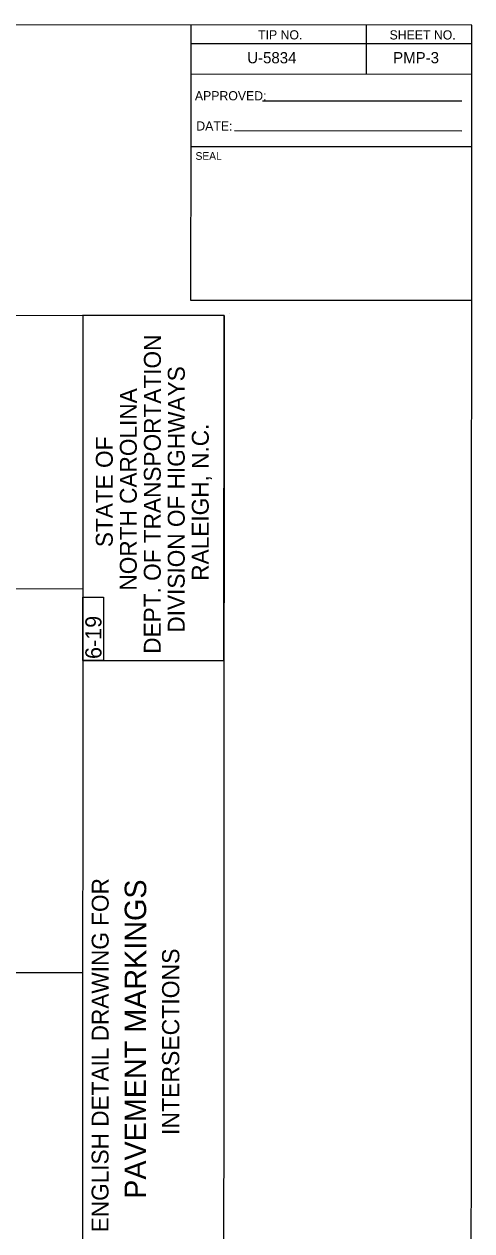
# Model space of a CAD drawing. Extents: x 50667 to 52386, y 46650 to 50479.
# Drawn here: x 52036 to 52336, y 47063 to 47871 of the extents above; entities that cross this region are included whole.
import ezdxf

# ---------------------------------------------------------------- set-up
doc = ezdxf.new("R2010")
doc.units = 0
for name, color, linetype in [('Default', 7, 'Continuous'), ('DEV TUBULAR MARKER SECTIONAL VIEW CELL', 7, 'Continuous'), ('Exist Right of Way Monument Text', 7, 'Continuous'), ('Exist Vertical Profile Ground Line', 7, 'Continuous'), ('Exist Vertical Profile Vertical Axis Label', 7, 'Continuous'), ('Old_Level_20', 7, 'Continuous'), ('Sheet Sticker Preliminary CELL', 7, 'Continuous'), ('Text', 7, 'Continuous'), ('TSCONFLICT', 7, 'Continuous')]:
    doc.layers.add(name, color=color, linetype=linetype)

msp = doc.modelspace()

# ---------------------------------------------------------------- linework, layer by layer
at = {"layer": 'Default'}
for p, q in [((52075.53, 47492.74), (50973.75, 47493.26)), ((52075.41, 47236.01), (50973.63, 47236.53))]:
    msp.add_line(p, q, dxfattribs=at)
at = {"layer": 'DEV TUBULAR MARKER SECTIONAL VIEW CELL'}
msp.add_lwpolyline([(50879.23, 46906.71), (50879.58, 47676.39), (52169.91, 47675.79), (52169.55, 46906.11)], close=True, dxfattribs=at)
at = {"layer": 'Exist Right of Way Monument Text'}
msp.add_lwpolyline([(52335.61, 47869.9), (50830.4, 47870.6), (50829.91, 46815.38), (52335.12, 46814.68)], close=True, dxfattribs=at)
at = {"layer": 'Exist Vertical Profile Ground Line'}
for p, q in [((52265.08, 47837.27), (52265.09, 47869.94)), ((52265.08, 47844.88), (52265.09, 47869.94)), ((52335.61, 47869.9), (52335.61, 47869.9)), ((52147.87, 47857.73), (52265.09, 47857.66)), ((52265.09, 47857.66), (52335.6, 47857.63)), ((52147.86, 47837.33), (52335.59, 47837.23)), ((52195.73, 47819.36), (52328.87, 47819.3)), ((52176.97, 47799.38), (52328.86, 47799.31))]:
    msp.add_line(p, q, dxfattribs=at)
at = {"layer": 'Old_Level_20'}
msp.add_line((52173.51, 47677.08), (52173.51, 47677.08), dxfattribs=at)
at = {"layer": 'Sheet Sticker Preliminary CELL'}
msp.add_lwpolyline([(52075.51, 47444.92), (52169.8, 47444.88), (52169.91, 47675.79), (52075.61, 47675.83), (52075.26, 46906.16), (52169.55, 46906.11), (52169.57, 46929.69), (52075.27, 46929.73), (52075.27, 46943.87), (52169.57, 46943.82)], dxfattribs=at)
at = {"layer": 'Text'}
msp.add_lwpolyline([(52089.26, 47444.92), (52075.51, 47444.92), (52075.53, 47487.28), (52089.28, 47487.28)], close=True, dxfattribs=at)
at = {"layer": 'TSCONFLICT'}
for p, q in [((52147.87, 47844.94), (52147.88, 47869.99)), ((52147.85, 47797.58), (52147.87, 47844.94)), ((52147.79, 47685.74), (52147.85, 47797.58)), ((52147.84, 47788.8), (52335.57, 47788.71)), ((52335.52, 47685.65), (52147.79, 47685.74))]:
    msp.add_line(p, q, dxfattribs=at)

# ---------------------------------------------------------------- texts
at = {"layer": 'Default'}
for s, height, p in [('PAVEMENT MARKINGS', 14.3748, (52117.79, 47084.82)), ('INTERSECTIONS', 11.4998, (52139.95, 47127.5))]:
    msp.add_text(s, height=height, rotation=89.97341, dxfattribs=at).set_placement(p)
at = {"layer": 'Exist Vertical Profile Ground Line'}
for s, height, p in [('TIP NO.', 6.134, (52192.7, 47860.39)), ('SHEET NO.', 6.134, (52280.6, 47860.34)), ('SEAL', 5.115, (52150.87, 47779.85))]:
    msp.add_text(s, height=height, rotation=359.96835, dxfattribs=at).set_placement(p)
at = {"layer": 'Exist Vertical Profile Vertical Axis Label'}
for s, p in [('APPROVED:', (52150.45, 47819.65)), ('DATE:', (52151.37, 47799.43))]:
    msp.add_text(s, height=6.134, rotation=359.96835, dxfattribs=at).set_placement(p)
at = {"layer": 'Sheet Sticker Preliminary CELL'}
for s, height, p in [('DEPT. OF TRANSPORTATION', 11.315, (52127.59, 47449.4)), ('DIVISION OF HIGHWAYS', 11.315, (52143.6, 47463.53)), ('NORTH CAROLINA', 11.315, (52111.56, 47491.67)), ('STATE OF', 11.315, (52095.52, 47520.72)), ('RALEIGH, N.C.', 11.315, (52159.67, 47498.26)), ('ENGLISH DETAIL DRAWING FOR', 11.3078, (52092.67, 47062.42))]:
    msp.add_text(s, height=height, rotation=89.97341, dxfattribs=at).set_placement(p)
at = {"layer": 'Text'}
msp.add_text('6-19', height=10.781, rotation=89.97341, dxfattribs=at).set_placement((52087.96, 47445.92))
at = {"layer": 'TSCONFLICT'}
for s, p in [('U-5834', (52185.43, 47844.39)), ('PMP-3', (52282.99, 47844.43))]:
    msp.add_text(s, height=7.5, rotation=359.96835, dxfattribs=at).set_placement(p)

doc.saveas('drawing.dxf')
